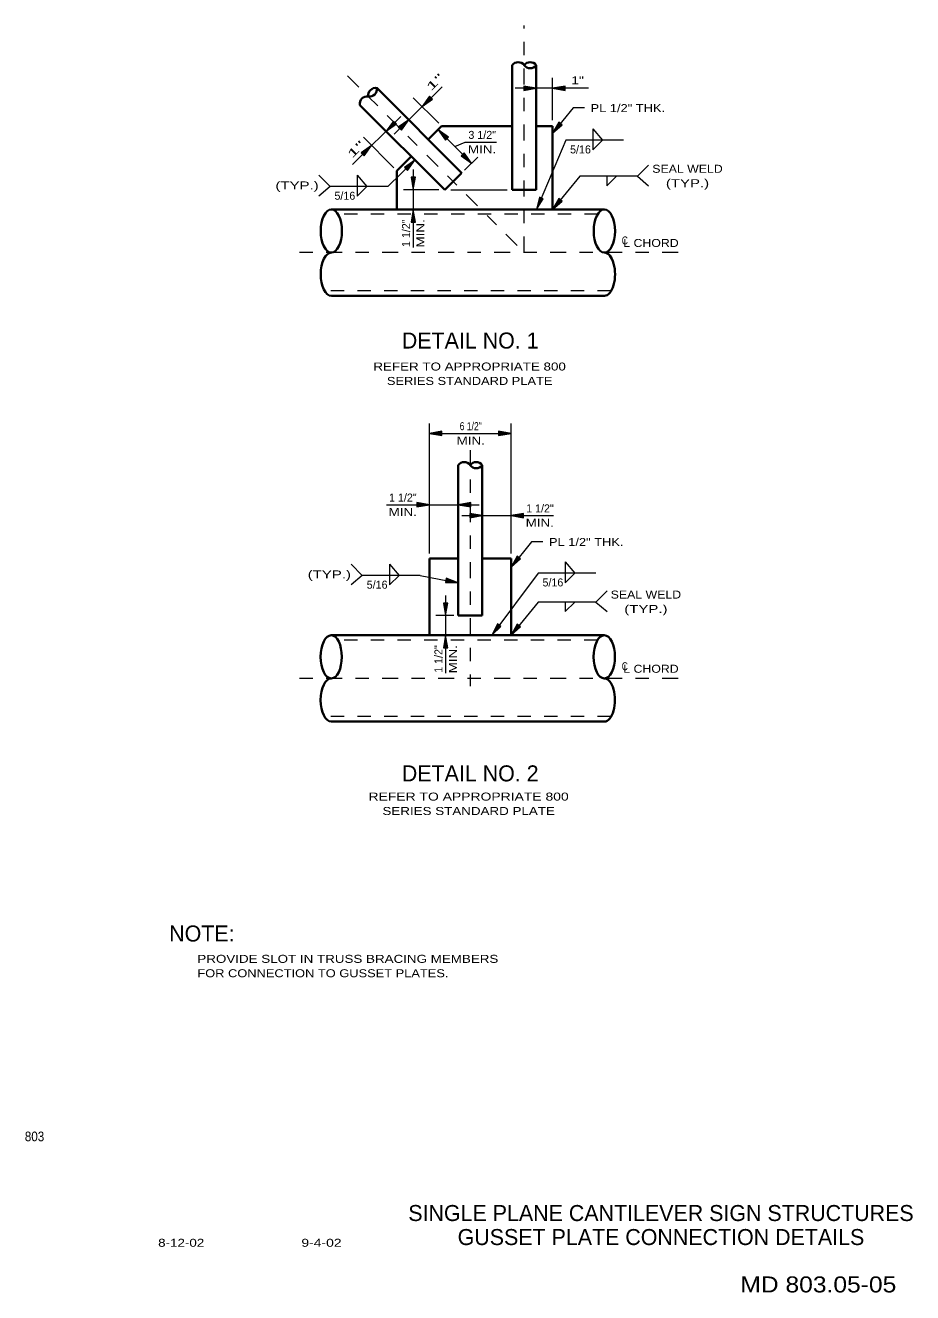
# Model space of a CAD drawing. Extents: x -34847.09 to -34840.43, y -181513.68 to -181504.18.
import ezdxf
from ezdxf.enums import TextEntityAlignment as Align

# ---------------------------------------------------------------- set-up
doc = ezdxf.new("R2010")
doc.units = 0
doc.header["$LTSCALE"] = 0.024
doc.linetypes.add('DOT_DASHED', pattern=[7.7, 5, -1.2, 0.3, -1.2])
doc.linetypes.add('MEDIUM_DASHED', pattern=[4.5, 3, -1.5])
for name, color, linetype, lineweight in [('1', 7, 'Continuous', 35), ('10', 7, 'Continuous', 13), ('13', 7, 'Continuous', 25), ('7', 7, 'Continuous', 35)]:
    doc.layers.add(name, color=color, linetype=linetype, lineweight=lineweight)

msp = doc.modelspace()

# ---------------------------------------------------------------- hatches: boundary and pattern name
at = {"layer": '10'}
for points in [[(-34844.033, -181504.736), (-34844.056, -181504.714), (-34844.111, -181504.791)], [(-34843.349, -181504.638), (-34843.349, -181504.67), (-34843.255, -181504.654)], [(-34843.038, -181504.67), (-34843.038, -181504.638), (-34843.132, -181504.654)], [(-34844.303, -181504.921), (-34844.326, -181504.899), (-34844.381, -181504.976)], [(-34844.289, -181504.945), (-34844.266, -181504.967), (-34844.211, -181504.89)], [(-34843.061, -181504.928), (-34843.085, -181504.908), (-34843.132, -181504.991)], [(-34843.936, -181505.042), (-34843.914, -181505.019), (-34843.991, -181504.964)], [(-34844.567, -181505.138), (-34844.544, -181505.16), (-34844.489, -181505.083)], [(-34844.243, -181505.247), (-34844.221, -181505.269), (-34844.164, -181505.193)], [(-34843.796, -181505.137), (-34843.818, -181505.16), (-34843.741, -181505.215)], [(-34844.161, -181505.321), (-34844.193, -181505.321), (-34844.177, -181505.415)], [(-34843.202, -181505.482), (-34843.231, -181505.469), (-34843.253, -181505.562)], [(-34843.061, -181505.499), (-34843.085, -181505.479), (-34843.132, -181505.562)], [(-34844.193, -181505.656), (-34844.161, -181505.656), (-34844.177, -181505.562)], [(-34843.962, -181507.256), (-34843.962, -181507.224), (-34844.056, -181507.24)], [(-34843.538, -181507.224), (-34843.538, -181507.256), (-34843.444, -181507.24)], [(-34844.15, -181507.759), (-34844.15, -181507.791), (-34844.056, -181507.775)], [(-34843.746, -181507.791), (-34843.746, -181507.759), (-34843.84, -181507.775)], [(-34843.754, -181507.84), (-34843.754, -181507.872), (-34843.66, -181507.856)], [(-34843.35, -181507.872), (-34843.35, -181507.84), (-34843.444, -181507.856)], [(-34843.373, -181508.18), (-34843.397, -181508.16), (-34843.444, -181508.243)], [(-34843.929, -181508.326), (-34843.935, -181508.357), (-34843.84, -181508.359)], [(-34843.918, -181508.512), (-34843.95, -181508.512), (-34843.934, -181508.606)], [(-34843.52, -181508.687), (-34843.546, -181508.668), (-34843.589, -181508.753)], [(-34843.373, -181508.69), (-34843.397, -181508.67), (-34843.444, -181508.753)], [(-34843.95, -181508.847), (-34843.918, -181508.847), (-34843.934, -181508.753)]]:
    msp.add_hatch(color=256, dxfattribs=at).paths.add_polyline_path(points)

# ---------------------------------------------------------------- linework, layer by layer
at = {"layer": '1', "linetype": 'DOT_DASHED', "lineweight": 13}
for p, q in [((-34843.345, -181505.885), (-34843.345, -181504.182)), ((-34844.67, -181504.56), (-34843.345, -181505.885)), ((-34842.19, -181505.885), (-34845.074, -181505.885)), ((-34843.75, -181507.366), (-34843.75, -181509.135)), ((-34842.19, -181509.076), (-34845.074, -181509.076))]:
    msp.add_line(p, q, dxfattribs=at)
at = {"layer": '1'}
for p, q in [((-34843.435, -181505.415), (-34843.435, -181504.481)), ((-34843.255, -181505.415), (-34843.255, -181504.481)), ((-34844.449, -181504.65), (-34843.814, -181505.289)), ((-34844.578, -181504.779), (-34843.941, -181505.415)), ((-34843.435, -181504.938), (-34843.965, -181504.938)), ((-34843.132, -181504.938), (-34843.255, -181504.938)), ((-34843.132, -181504.938), (-34843.132, -181505.562)), ((-34844.3, -181505.562), (-34844.3, -181505.272)), ((-34843.435, -181505.415), (-34843.255, -181505.415)), ((-34842.744, -181505.562), (-34844.791, -181505.562)), ((-34842.744, -181506.209), (-34844.791, -181506.209)), ((-34843.84, -181507.478), (-34843.84, -181508.606)), ((-34843.66, -181507.478), (-34843.66, -181508.606)), ((-34844.056, -181508.177), (-34844.056, -181508.753)), ((-34843.84, -181508.177), (-34844.056, -181508.177)), ((-34843.444, -181508.177), (-34843.66, -181508.177)), ((-34843.444, -181508.177), (-34843.444, -181508.753)), ((-34843.66, -181508.606), (-34843.84, -181508.606)), ((-34842.745, -181508.753), (-34844.792, -181508.753)), ((-34842.745, -181509.4), (-34844.792, -181509.4))]:
    msp.add_line(p, q, dxfattribs=at)
at = {"layer": '1', "linetype": 'MEDIUM_DASHED', "lineweight": 13}
for p, q in [((-34842.794, -181505.598), (-34844.741, -181505.598)), ((-34842.695, -181506.172), (-34844.842, -181506.172)), ((-34842.795, -181508.789), (-34844.742, -181508.789)), ((-34842.696, -181509.363), (-34844.843, -181509.363))]:
    msp.add_line(p, q, dxfattribs=at)
at = {"layer": '1'}
for centre in [(-34844.79134, -181505.72364), (-34842.74366, -181505.72364), (-34844.79234, -181508.91464), (-34842.74466, -181508.91464)]:
    msp.add_ellipse(centre, major_axis=(0, -0.16179), ratio=0.492739, dxfattribs=at)
for centre, start_param, end_param in [((-34844.79134, -181506.04722), 3.1415927, 6.2831853), ((-34842.74366, -181506.04722), 6.2831853, 9.424778), ((-34844.79234, -181509.23822), 3.1415927, 6.2831853), ((-34842.74466, -181509.23822), 6.2831853, 9.424778)]:
    msp.add_ellipse(centre, major_axis=(0, -0.16179), ratio=0.492739, start_param=start_param, end_param=end_param, dxfattribs=at)
at = {"layer": '10'}
for p, q in [((-34843.132, -181504.893), (-34843.132, -181504.575)), ((-34843.961, -181504.642), (-34844.319, -181504.998)), ((-34842.864, -181504.654), (-34843.413, -181504.654)), ((-34844.177, -181504.725), (-34843.986, -181504.916)), ((-34844.271, -181504.866), (-34844.632, -181505.226)), ((-34843.991, -181504.964), (-34843.741, -181505.215)), ((-34842.83, -181504.958), (-34842.758, -181505.042)), ((-34844.55, -181505.021), (-34844.322, -181505.25)), ((-34843.034, -181505.042), (-34843.253, -181505.562)), ((-34842.601, -181505.042), (-34843.034, -181505.042)), ((-34844.177, -181505.263), (-34844.177, -181505.846)), ((-34842.496, -181505.313), (-34842.412, -181505.229)), ((-34844.801, -181505.389), (-34844.885, -181505.305)), ((-34844.597, -181505.305), (-34844.525, -181505.389)), ((-34842.929, -181505.313), (-34843.132, -181505.562)), ((-34842.496, -181505.313), (-34842.929, -181505.313)), ((-34842.725, -181505.385), (-34842.653, -181505.313)), ((-34842.725, -181505.313), (-34842.725, -181505.385)), ((-34842.496, -181505.313), (-34842.412, -181505.385)), ((-34844.801, -181505.389), (-34844.885, -181505.461)), ((-34844.368, -181505.389), (-34844.801, -181505.389)), ((-34843.985, -181505.415), (-34844.251, -181505.415)), ((-34843.896, -181505.415), (-34843.473, -181505.415)), ((-34844.056, -181508.139), (-34844.056, -181507.166)), ((-34843.444, -181508.139), (-34843.444, -181507.166)), ((-34844.056, -181507.24), (-34843.444, -181507.24)), ((-34844.377, -181507.775), (-34843.684, -181507.775)), ((-34843.813, -181507.856), (-34843.125, -181507.856)), ((-34843.29, -181508.053), (-34843.444, -181508.243)), ((-34843.205, -181508.053), (-34843.29, -181508.053)), ((-34844.559, -181508.304), (-34844.643, -181508.22)), ((-34844.355, -181508.22), (-34844.283, -181508.304)), ((-34843.037, -181508.203), (-34842.965, -181508.287)), ((-34844.559, -181508.304), (-34844.643, -181508.376)), ((-34844.126, -181508.304), (-34844.559, -181508.304)), ((-34844.126, -181508.304), (-34843.84, -181508.359)), ((-34843.241, -181508.287), (-34843.589, -181508.753)), ((-34842.808, -181508.287), (-34843.241, -181508.287)), ((-34842.808, -181508.504), (-34842.724, -181508.42)), ((-34843.934, -181508.454), (-34843.934, -181509.037)), ((-34843.037, -181508.576), (-34842.965, -181508.504)), ((-34843.037, -181508.504), (-34843.037, -181508.576)), ((-34842.808, -181508.504), (-34842.724, -181508.576)), ((-34843.873, -181508.606), (-34844.008, -181508.606))]:
    msp.add_line(p, q, dxfattribs=at)
for points in [[(-34844.033, -181504.736), (-34844.056, -181504.714), (-34844.111, -181504.791)], [(-34843.349, -181504.638), (-34843.349, -181504.67), (-34843.255, -181504.654)], [(-34843.038, -181504.67), (-34843.038, -181504.638), (-34843.132, -181504.654)], [(-34844.303, -181504.921), (-34844.326, -181504.899), (-34844.381, -181504.976)], [(-34844.289, -181504.945), (-34844.266, -181504.967), (-34844.211, -181504.89)], [(-34843.061, -181504.928), (-34843.085, -181504.908), (-34843.132, -181504.991)], [(-34843.936, -181505.042), (-34843.914, -181505.019), (-34843.991, -181504.964)], [(-34844.567, -181505.138), (-34844.544, -181505.16), (-34844.489, -181505.083)], [(-34844.243, -181505.247), (-34844.221, -181505.269), (-34844.164, -181505.193)], [(-34843.796, -181505.137), (-34843.818, -181505.16), (-34843.741, -181505.215)], [(-34844.161, -181505.321), (-34844.193, -181505.321), (-34844.177, -181505.415)], [(-34843.202, -181505.482), (-34843.231, -181505.469), (-34843.253, -181505.562)], [(-34843.061, -181505.499), (-34843.085, -181505.479), (-34843.132, -181505.562)], [(-34844.193, -181505.656), (-34844.161, -181505.656), (-34844.177, -181505.562)], [(-34843.962, -181507.256), (-34843.962, -181507.224), (-34844.056, -181507.24)], [(-34843.538, -181507.224), (-34843.538, -181507.256), (-34843.444, -181507.24)], [(-34844.15, -181507.759), (-34844.15, -181507.791), (-34844.056, -181507.775)], [(-34843.746, -181507.791), (-34843.746, -181507.759), (-34843.84, -181507.775)], [(-34843.754, -181507.84), (-34843.754, -181507.872), (-34843.66, -181507.856)], [(-34843.35, -181507.872), (-34843.35, -181507.84), (-34843.444, -181507.856)], [(-34843.373, -181508.18), (-34843.397, -181508.16), (-34843.444, -181508.243)], [(-34843.929, -181508.326), (-34843.935, -181508.357), (-34843.84, -181508.359)], [(-34843.918, -181508.512), (-34843.95, -181508.512), (-34843.934, -181508.606)], [(-34843.52, -181508.687), (-34843.546, -181508.668), (-34843.589, -181508.753)], [(-34843.373, -181508.69), (-34843.397, -181508.67), (-34843.444, -181508.753)], [(-34843.95, -181508.847), (-34843.918, -181508.847), (-34843.934, -181508.753)]]:
    msp.add_lwpolyline(points, close=True, dxfattribs=at)
for points in [[(-34842.893, -181504.801), (-34842.978, -181504.801), (-34843.132, -181504.991)], [(-34842.83, -181504.958), (-34842.83, -181505.114), (-34842.758, -181505.042)], [(-34843.866, -181505.09), (-34843.789, -181505.057), (-34843.553, -181505.057)], [(-34844.597, -181505.305), (-34844.597, -181505.461), (-34844.525, -181505.389)], [(-34844.355, -181508.22), (-34844.355, -181508.376), (-34844.283, -181508.304)], [(-34843.037, -181508.203), (-34843.037, -181508.359), (-34842.965, -181508.287)], [(-34842.808, -181508.504), (-34843.241, -181508.504), (-34843.444, -181508.753)]]:
    msp.add_lwpolyline(points, dxfattribs=at)
at = {"layer": '13'}
for p, q in [((-34844.368, -181505.389), (-34844.164, -181505.193)), ((-34843.694, -181505.17), (-34843.792, -181505.267))]:
    msp.add_line(p, q, dxfattribs=at)
at = {"layer": '7'}
for p, q in [((-34844.064, -181505.037), (-34843.965, -181504.938)), ((-34844.3, -181505.272), (-34844.192, -181505.164)), ((-34843.815, -181505.289), (-34843.941, -181505.415))]:
    msp.add_line(p, q, dxfattribs=at)
for centre, start, end in [((-34843.39, -181504.5135), 35.83765, 144.16235), ((-34843.3, -181504.5135), 35.83765, 144.16235), ((-34843.3, -181504.4485), 215.83765, 324.16235), ((-34844.5232, -181504.77016), 80.83765, 189.16235), ((-34844.45956, -181504.70652), 80.83765, 189.16235), ((-34844.50552, -181504.66056), 260.83765, 9.16235), ((-34843.795, -181507.5105), 35.83765, 144.16235), ((-34843.705, -181507.5105), 35.83765, 144.16235), ((-34843.705, -181507.4455), 215.83765, 324.16235)]:
    msp.add_arc(centre, 0.05551, start, end, dxfattribs=at)

# ---------------------------------------------------------------- texts
at = {"layer": '13'}
for s, rotation, width, p in [('1"', 45, 1.95, (-34843.99371, -181504.62871)), ('1"', 45, 1.95, (-34844.58571, -181505.13271)), ('MIN.', 90, 1.25, (-34844.093, -181505.741)), ('MIN.', 90, 1.25, (-34843.85, -181508.932))]:
    msp.add_text(s, height=0.06, rotation=rotation, dxfattribs=dict(at, width=width)).set_placement(p, align=Align.CENTER)
for s, height, width, p in [('1"', 0.06, 1.3, (-34842.945, -181504.624)), ('PL 1/2" THK.', 0.06, 1.2, (-34842.568, -181504.832)), ('MIN.', 0.06, 1.25, (-34843.661, -181505.141)), ('SEAL WELD', 0.06, 1.15, (-34842.1205, -181505.287)), ('(TYP.)', 0.06, 1.4, (-34845.0485, -181505.412)), ('(TYP.)', 0.06, 1.4, (-34842.1205, -181505.395)), ('C', 0.06, 0.8, (-34842.5905, -181505.824)), ('L CHORD', 0.06, 1.15, (-34842.3945, -181505.843)), ('REFER TO APPROPRIATE 800', 0.06, 1.25, (-34843.7545, -181506.769)), ('SERIES STANDARD PLATE', 0.06, 1.2, (-34843.754, -181506.877)), ('6 1/2"', 0.06, 0.8, (-34843.746, -181507.216)), ('MIN.', 0.06, 1.25, (-34843.746, -181507.324)), ('MIN.', 0.06, 1.25, (-34844.256, -181507.859)), ('MIN.', 0.06, 1.25, (-34843.228, -181507.94)), ('PL 1/2" THK.', 0.06, 1.2, (-34842.88, -181508.084)), ('(TYP.)', 0.06, 1.4, (-34844.8065, -181508.327)), ('SEAL WELD', 0.06, 1.15, (-34842.4325, -181508.478)), ('(TYP.)', 0.06, 1.4, (-34842.4325, -181508.586)), ('C', 0.06, 0.8, (-34842.5905, -181509.015)), ('L CHORD', 0.06, 1.15, (-34842.3945, -181509.034)), ('REFER TO APPROPRIATE 800 ', 0.06, 1.3, (-34843.7475, -181509.992)), ('SERIES STANDARD PLATE ', 0.06, 1.25, (-34843.7475, -181510.1)), ('803', 0.07251, 0.9, (-34847.017, -181512.545)), ('MD 803.05-05', 0.12, 1.15, (-34841.1395, -181513.678))]:
    msp.add_text(s, height=height, dxfattribs=dict(at, width=width)).set_placement(p, align=Align.CENTER)
for s, height, p in [('3 1/2"', 0.06, (-34843.66, -181505.033)), ('DETAIL NO. 1', 0.12, (-34843.75, -181506.604)), ('1 1/2"', 0.06, (-34844.255, -181507.751)), ('1 1/2"', 0.06, (-34843.227, -181507.832)), ('DETAIL NO. 2', 0.12, (-34843.75, -181509.848)), ('NOTE:', 0.12, (-34845.762, -181511.048)), ('SINGLE PLANE CANTILEVER SIGN STRUCTURES', 0.12, (-34842.3195, -181513.143)), ('GUSSET PLATE CONNECTION DETAILS', 0.12, (-34842.3195, -181513.323))]:
    msp.add_text(s, height=height, dxfattribs=at).set_placement(p, align=Align.CENTER)
for p in [(-34843.001, -181505.142), (-34844.768, -181505.489), (-34843.208, -181508.387), (-34844.526, -181508.404)]:
    msp.add_text('5/16', height=0.06002, dxfattribs=at).set_placement(p)
for p in [(-34844.201, -181505.74), (-34843.958, -181508.931)]:
    msp.add_text('1 1/2"', height=0.06, rotation=90, dxfattribs=at).set_placement(p, align=Align.CENTER)
for s, width, p in [('PROVIDE SLOT IN TRUSS BRACING MEMBERS', 1.25, (-34845.796, -181511.208)), ('FOR CONNECTION TO GUSSET PLATES.', 1.2, (-34845.796, -181511.316)), ('8-12-02', 1.25, (-34846.09, -181513.336)), ('9-4-02', 1.3, (-34845.016, -181513.336))]:
    msp.add_text(s, height=0.06, dxfattribs=dict(at, width=width)).set_placement(p)

doc.saveas('drawing.dxf')
